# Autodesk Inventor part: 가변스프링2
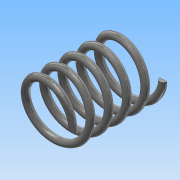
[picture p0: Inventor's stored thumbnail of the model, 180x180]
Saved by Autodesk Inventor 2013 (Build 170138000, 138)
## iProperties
Created: 2018-10
Part Number: 가변스프링2
Material: 스테인리스강
Document SubType Name: Modeling
Designer: Administrator
Density: 8.08 g/cm^3
Mass: 6.269 g
Surface Area: 15.7689 cm^2
Volume: 0.775866 cm^3
Author: Administrator
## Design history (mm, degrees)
sketch "스케치1"
  geometry: L1 (0, 0)-(0, 26.302); L2 (0, 0)-(8, 0); L3 (0, 26.302)-(8, 26.302); C1 r 1 at (8, 0); 1 further point
  constraints: 6 end point, 2 coincident, 1 centre point, 1 parallel, 1 perpendicular, 1 vertical
  dimensions: "d0" = 26.3022 distance of L1.start L1.end (derived); "d1" = 8 distance of L1.start L2.end; "d2" = 2 diameter of C1; "d3" = 8 distance of L1.end L3.end
feature "코일1" sketch "스케치1" pitch "d4" = 10; turns "d6" = 5; dims "d5" = 26.3022 (= d0), "d7" = 0, angle "d8" = 90 deg, angle "d9" = 90 deg, "d10" = 0, "d11" = 0
sketch "스케치2"
  geometry: L1 (0, -10)-(26.302, -10); L2 (26.302, -10)-(26.302, 10); L3 (26.302, 10)-(0, 10); L4 (0, 10)-(0, -10); 2 further points
  constraints: 8 end point, 2 parallel, 1 coincident, 1 horizontal, 1 midpoint, 1 perpendicular
  dimensions: "d12" = 20 distance of L3.end L1.start; "d14" = 26.3022 distance of L1.start L1.end (derived)
extrude "돌출1" sketch "스케치2" stored distance "d15" = 0; taper "d16" = 0 deg
node "솔리드1"
